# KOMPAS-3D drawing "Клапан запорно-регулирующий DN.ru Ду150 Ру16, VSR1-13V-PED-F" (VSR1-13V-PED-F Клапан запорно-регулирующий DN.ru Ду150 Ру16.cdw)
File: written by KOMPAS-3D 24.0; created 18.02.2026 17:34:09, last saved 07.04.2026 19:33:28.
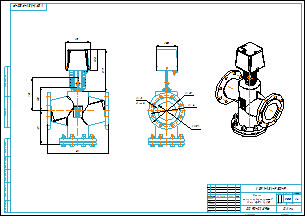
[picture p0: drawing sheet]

Document properties: Автор: R2D2; Форматы листов документа: A2; Полное имя файла: VSR1-13V-PED-F Клапан запорно-регулирующий DN.ru Ду150 Ру16.m3d; Масса: 56.6; Наименование: Клапан запорно-регулирующий DN.ru Ду150 Ру16; Количество листов документа: 1; Примечание: D090-02896

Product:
- Part/product: Клапан запорно-регулирующий DN.ru Ду150 Ру16  | designation VSR1-13V-PED-F
    Масса: 56.6
    Раздел спецификации: Прочие изделия
    Примечание: D090-02896

Views: Вид 1, Спереди
Referenced files in E:\Работа\Зайцев\Солянка\VSR1-13V-PED-F Клапан запорно-регулирующий DN.ru\DN15\DN15 Kv0.16\: VSR1-13V-PED-F Клапан запорно-регулирующий DN.ru Ду15 Ру16.m3d
Referenced files in E:\Работа\Зайцев\Солянка\VSR1-13V-PED-F Клапан запорно-регулирующий DN.ru\DN150\: VSR1-13V-PED-F Клапан запорно-регулирующий DN.ru Ду150 Ру16.m3d
Referenced files in E:\Работа\Зайцев\Для компаса\: чертеж DN.ru А3.cdt
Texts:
  Линейный размер
  VSR1-13V-PED-F
  чертеж DN.ru А3.cdt
  Клапан
  запорно-регулирующий
  DN.ru Ду150 Ру16
  Клапан запорно-регулирующий DN.ru Ду150 Ру16
  VSR1-13V-PED-F Клапан запорно-регулирующий DN.ru Ду150 Ру16
Dimensions and other numbers on the sheet: 0; 3; 2; 4; 480; 262; 185; 260; 190; 327; 158; 1:4; 1; 56,6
